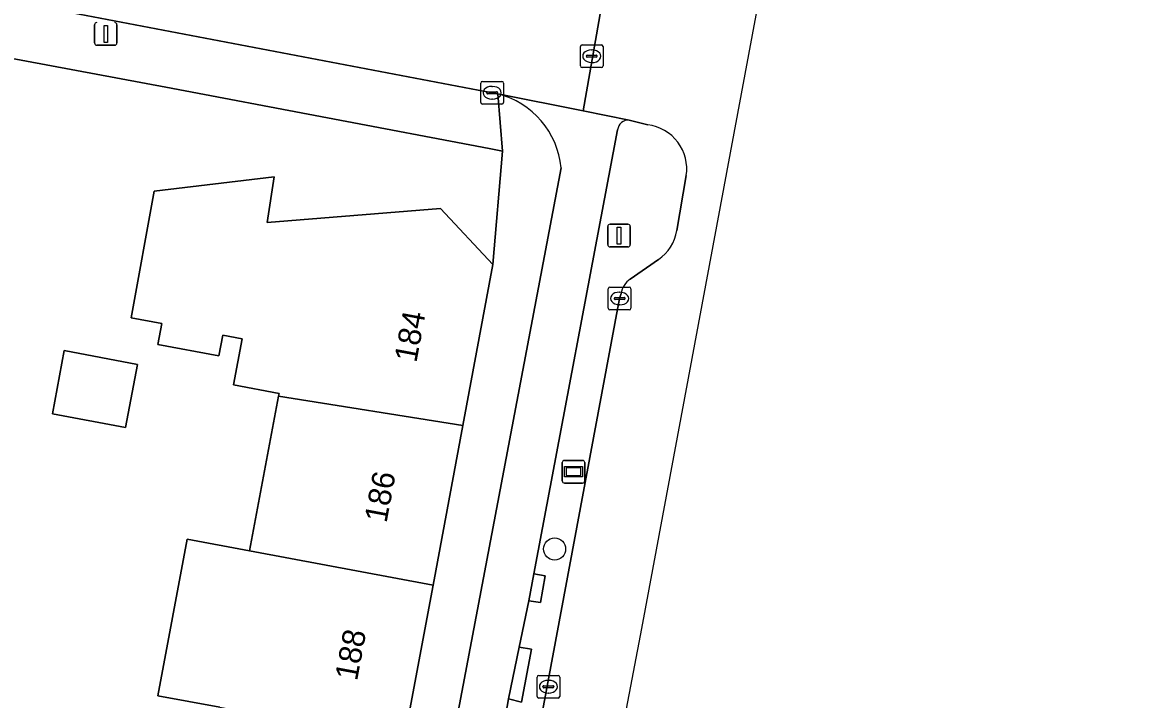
# Model space of a CAD drawing. Extents: x 161258 to 161838, y 380833 to 381727.
# Drawn here: x 161786.15 to 161835.77, y 381501.62 to 381531.46 of the extents above; entities that cross this region are included whole.
import ezdxf

# ---------------------------------------------------------------- set-up
doc = ezdxf.new("R2010")
doc.units = 0
for name, color, linetype in [('IMGEO_Berm_open', 7, 'Continuous'), ('IMGEO_Boom', 7, 'Continuous'), ('IMGEO_Erf', 7, 'Continuous'), ('IMGEO_Fietspad_open', 7, 'Continuous'), ('IMGEO_Kolk', 7, 'Continuous'), ('IMGEO_Lichtmast', 7, 'Continuous'), ('IMGEO_Pand', 7, 'Continuous'), ('IMGEO_Pand_nummerreeks', 7, 'Continuous'), ('IMGEO_Reclamebord', 7, 'Continuous'), ('IMGEO_Rijbaan_lokaal_open', 7, 'Continuous'), ('IMGEO_Rijbaan_regionaal_gesloten', 7, 'Continuous'), ('IMGEO_Rioolput', 7, 'Continuous'), ('IMGEO_Voetpad_open', 7, 'Continuous')]:
    doc.layers.add(name, color=color, linetype=linetype)

msp = doc.modelspace()

# ---------------------------------------------------------------- linework, layer by layer
at = {"layer": 'IMGEO_Berm_open'}
for points in [[(161813.737, 381526.947), (161812.916, 381527.15)], [(161812.402, 381526.729), (161808.703, 381507.157), (161809.2, 381507.077), (161809, 381505.901), (161808.478, 381505.969), (161808.057, 381503.928), (161808.598, 381503.831), (161808.168, 381501.508), (161807.583, 381501.645), (161807.282, 381499.872)], [(161815.011, 381522.292), (161815.427, 381524.711)], [(161812.951, 381520.152), (161814.198, 381521.007)], [(161805.513, 381482.046), (161808.875, 381500), (161812.487, 381519.293), (161812.558, 381519.511)]]:
    msp.add_lwpolyline(points, dxfattribs=at)
for centre, radius, start, end in [((161812.861, 381526.693), 0.46, 83.1072, 175.5323), ((161813.485, 381525), 1.964, 351.5445, 82.6204), ((161813.139, 381522.576), 1.893, 304.001, 351.3572), ((161813.495, 381519.377), 0.947, 125.0851, 171.8896)]:
    msp.add_arc(centre, radius, start, end, dxfattribs=at)
at = {"layer": 'IMGEO_Boom'}
msp.add_circle((161809.62, 381508.253), 0.489, dxfattribs=at)
at = {"layer": 'IMGEO_Erf'}
msp.add_lwpolyline([(161794.859, 381501.276), (161792.127, 381501.787), (161793.418, 381508.689), (161796.159, 381508.176), (161797.442, 381514.985), (161797.465, 381515.106), (161795.457, 381515.485), (161795.842, 381517.523), (161794.982, 381517.685), (161794.808, 381516.76), (161792.115, 381517.269), (161792.29, 381518.193), (161790.946, 381518.447), (161791.954, 381524.02), (161797.254, 381524.651), (161796.944, 381522.646), (161804.585, 381523.258), (161806.898, 381520.791), (161807.325, 381525.789), (161806.742, 381525.9), (161792.473, 381528.615), (161780.173, 381530.897)], dxfattribs=at)
msp.add_lwpolyline([(161787.468, 381514.215), (161787.994, 381516.997), (161791.223, 381516.388), (161790.697, 381513.606)], close=True, dxfattribs=at)
at = {"layer": 'IMGEO_Fietspad_open'}
for points in [[(161812.916, 381527.15), (161810.875, 381527.563), (161807.12, 381528.313)], [(161807.282, 381499.872), (161807.583, 381501.645), (161808.057, 381503.928), (161808.478, 381505.969), (161808.703, 381507.157), (161812.402, 381526.729)], [(161809.91, 381525.057), (161805.168, 381500)]]:
    msp.add_lwpolyline(points, dxfattribs=at)
for centre, radius, start, end in [((161806.195, 381524.697), 3.732, 5.5304, 75.6548), ((161812.861, 381526.693), 0.46, 83.1072, 175.5323)]:
    msp.add_arc(centre, radius, start, end, dxfattribs=at)
at = {"layer": 'IMGEO_Kolk'}
for p, q in [((161806.366, 381527.935), (161806.366, 381528.787)), ((161806.441, 381528.861), (161807.293, 381528.861)), ((161807.367, 381528.787), (161807.367, 381527.935)), ((161806.625, 381528.355), (161806.625, 381528.367)), ((161807.063, 381528.318), (161806.665, 381528.318)), ((161806.668, 381528.404), (161807.066, 381528.404)), ((161806.854, 381528.641), (161806.879, 381528.641)), ((161807.109, 381528.367), (161807.109, 381528.355)), ((161807.293, 381527.861), (161806.441, 381527.861)), ((161806.877, 381528.081), (161806.852, 381528.081)), ((161811.989, 381518.868), (161811.989, 381519.72)), ((161812.064, 381519.794), (161812.916, 381519.794)), ((161812.291, 381519.337), (161812.689, 381519.337)), ((161812.477, 381519.574), (161812.502, 381519.574)), ((161812.99, 381519.72), (161812.99, 381518.868)), ((161812.248, 381519.288), (161812.248, 381519.3)), ((161812.686, 381519.251), (161812.288, 381519.251)), ((161812.5, 381519.014), (161812.475, 381519.014)), ((161812.732, 381519.3), (161812.732, 381519.288)), ((161812.916, 381518.794), (161812.064, 381518.794)), ((161808.848, 381501.756), (161808.848, 381502.608)), ((161808.923, 381502.682), (161809.775, 381502.682)), ((161809.336, 381502.462), (161809.361, 381502.462)), ((161809.849, 381502.608), (161809.849, 381501.756)), ((161809.107, 381502.176), (161809.107, 381502.188)), ((161809.545, 381502.139), (161809.147, 381502.139)), ((161809.15, 381502.225), (161809.548, 381502.225)), ((161809.591, 381502.188), (161809.591, 381502.176)), ((161809.775, 381501.682), (161808.923, 381501.682)), ((161809.359, 381501.902), (161809.334, 381501.902))]:
    msp.add_line(p, q, dxfattribs=at)
for points in [[(161806.366, 381527.935), (161806.366, 381528.787)], [(161806.441, 381528.861), (161807.293, 381528.861)], [(161807.367, 381528.787), (161807.367, 381527.935)], [(161807.293, 381527.861), (161806.441, 381527.861)], [(161811.989, 381518.868), (161811.989, 381519.72)], [(161812.064, 381519.794), (161812.916, 381519.794)], [(161812.99, 381519.72), (161812.99, 381518.868)], [(161812.916, 381518.794), (161812.064, 381518.794)], [(161808.848, 381501.756), (161808.848, 381502.608)], [(161808.923, 381502.682), (161809.775, 381502.682)], [(161809.849, 381502.608), (161809.849, 381501.756)], [(161809.775, 381501.682), (161808.923, 381501.682)]]:
    msp.add_lwpolyline(points, dxfattribs=at)
for centre, radius, start, end in [((161806.443, 381528.785), 0.0765, 91.552, 178.448), ((161806.443, 381528.785), 0.0765, 91.552, 178.448), ((161807.291, 381528.785), 0.0765, 1.552, 88.448), ((161807.291, 381528.785), 0.0765, 1.552, 88.448), ((161806.665, 381528.364), 0.0403, 85.8775, 175.7526), ((161806.662, 381528.354), 0.0366, 178.938, 274.7102), ((161807.066, 381528.361), 0.043, 264.8664, 352.4533), ((161807.07, 381528.366), 0.0386, 1.7309, 96.639), ((161806.443, 381527.937), 0.0765, 181.552, 268.448), ((161806.443, 381527.937), 0.0765, 181.552, 268.448), ((161807.291, 381527.937), 0.0765, 271.552, 358.448), ((161807.291, 381527.937), 0.0765, 271.552, 358.448), ((161812.066, 381519.718), 0.0765, 91.552, 178.448), ((161812.066, 381519.718), 0.0765, 91.552, 178.448), ((161812.288, 381519.297), 0.0403, 85.8775, 175.7526), ((161812.693, 381519.299), 0.0386, 1.7309, 96.639), ((161812.914, 381519.718), 0.0765, 1.552, 88.448), ((161812.914, 381519.718), 0.0765, 1.552, 88.448), ((161812.066, 381518.87), 0.0765, 181.552, 268.448), ((161812.066, 381518.87), 0.0765, 181.552, 268.448), ((161812.285, 381519.287), 0.0366, 178.938, 274.7102), ((161812.689, 381519.294), 0.043, 264.8664, 352.4533), ((161812.914, 381518.87), 0.0765, 271.552, 358.448), ((161812.914, 381518.87), 0.0765, 271.552, 358.448), ((161808.925, 381502.606), 0.0765, 91.552, 178.448), ((161808.925, 381502.606), 0.0765, 91.552, 178.448), ((161809.773, 381502.606), 0.0765, 1.552, 88.448), ((161809.773, 381502.606), 0.0765, 1.552, 88.448), ((161809.147, 381502.185), 0.0403, 85.8775, 175.7526), ((161809.144, 381502.175), 0.0366, 178.938, 274.7102), ((161809.548, 381502.182), 0.043, 264.8664, 352.4533), ((161809.552, 381502.187), 0.0386, 1.7309, 96.639), ((161808.925, 381501.758), 0.0765, 181.552, 268.448), ((161808.925, 381501.758), 0.0765, 181.552, 268.448), ((161809.773, 381501.758), 0.0765, 271.552, 358.448), ((161809.773, 381501.758), 0.0765, 271.552, 358.448)]:
    msp.add_arc(centre, radius, start, end, dxfattribs=at)
for centre, major_axis, ratio, start_param, end_param in [((161806.853, 381528.361), (-0.387, 0.002), 0.722429, 4.712389, 7.853982), ((161806.878, 381528.361), (-0.39, 0.002), 0.717154, 1.570796, 4.712389), ((161812.476, 381519.294), (-0.387, 0.002), 0.722429, 4.712389, 7.853982), ((161812.501, 381519.294), (-0.39, 0.002), 0.717154, 1.570796, 4.712389), ((161809.335, 381502.182), (-0.387, 0.002), 0.722429, 4.712389, 7.853982), ((161809.36, 381502.182), (-0.39, 0.002), 0.717154, 1.570796, 4.712389)]:
    msp.add_ellipse(centre, major_axis=major_axis, ratio=ratio, start_param=start_param, end_param=end_param, dxfattribs=at)
at = {"layer": 'IMGEO_Lichtmast'}
for p, q in [((161789.327, 381530.559), (161789.327, 381531.359)), ((161789.327, 381531.359), (161789.327, 381530.559)), ((161790.317, 381531.359), (161790.317, 381530.559)), ((161790.317, 381530.559), (161790.317, 381531.359)), ((161790.217, 381530.459), (161789.427, 381530.459)), ((161789.427, 381530.459), (161790.217, 381530.459)), ((161811.967, 381521.669), (161811.967, 381522.469)), ((161811.967, 381522.469), (161811.967, 381521.669)), ((161812.067, 381522.569), (161812.857, 381522.569)), ((161812.857, 381522.569), (161812.067, 381522.569)), ((161812.957, 381522.469), (161812.957, 381521.669)), ((161812.957, 381521.669), (161812.957, 381522.469)), ((161812.857, 381521.569), (161812.067, 381521.569)), ((161812.067, 381521.569), (161812.857, 381521.569))]:
    msp.add_line(p, q, dxfattribs=at)
for points in [[(161789.747, 381531.334), (161789.897, 381531.334), (161789.897, 381530.584), (161789.747, 381530.584), (161789.747, 381531.334)], [(161812.387, 381522.444), (161812.537, 381522.444), (161812.537, 381521.694), (161812.387, 381521.694), (161812.387, 381522.444)]]:
    msp.add_lwpolyline(points, dxfattribs=at)
for centre, start, end in [((161789.427, 381531.359), 90, 180), ((161789.427, 381531.359), 90, 180), ((161790.217, 381531.359), 0, 90), ((161790.217, 381531.359), 360, 90), ((161789.427, 381530.559), 180, 270), ((161789.427, 381530.559), 180, 270), ((161790.217, 381530.559), 270, 0), ((161790.217, 381530.559), 270, 0), ((161812.067, 381522.469), 90, 180), ((161812.067, 381522.469), 90, 180), ((161812.857, 381522.469), 0, 90), ((161812.857, 381522.469), 360, 90), ((161812.067, 381521.669), 180, 270), ((161812.067, 381521.669), 180, 270), ((161812.857, 381521.669), 270, 0), ((161812.857, 381521.669), 270, 0)]:
    msp.add_arc(centre, 0.1, start, end, dxfattribs=at)
at = {"layer": 'IMGEO_Pand'}
for points in [[(161806.898, 381520.791), (161804.585, 381523.258), (161796.944, 381522.646), (161797.254, 381524.651), (161791.954, 381524.02), (161790.946, 381518.447), (161792.29, 381518.193), (161792.115, 381517.269), (161794.808, 381516.76), (161794.982, 381517.685), (161795.842, 381517.523), (161795.457, 381515.485), (161797.465, 381515.106), (161797.442, 381514.985), (161805.574, 381513.691)], [(161787.468, 381514.215), (161790.697, 381513.606), (161791.223, 381516.388), (161787.994, 381516.997)], [(161804.264, 381506.66), (161805.574, 381513.691), (161797.442, 381514.985), (161796.159, 381508.176)], [(161804.264, 381506.66), (161796.159, 381508.176), (161793.418, 381508.689), (161792.127, 381501.787), (161794.859, 381501.276), (161801.684, 381500), (161802.977, 381499.759), (161803.022, 381500)]]:
    msp.add_lwpolyline(points, close=True, dxfattribs=at)
at = {"layer": 'IMGEO_Reclamebord'}
for p, q in [((161809.96, 381511.259), (161809.96, 381512.059)), ((161809.96, 381512.059), (161809.96, 381511.259)), ((161810.06, 381512.159), (161810.85, 381512.159)), ((161810.85, 381512.159), (161810.06, 381512.159)), ((161810.95, 381512.059), (161810.95, 381511.259)), ((161810.95, 381511.259), (161810.95, 381512.059)), ((161810.85, 381511.159), (161810.06, 381511.159)), ((161810.06, 381511.159), (161810.85, 381511.159))]:
    msp.add_line(p, q, dxfattribs=at)
for points in [[(161810.061, 381511.891), (161810.849, 381511.891), (161810.849, 381511.427), (161810.061, 381511.427), (161810.061, 381511.891)], [(161810.126, 381511.826), (161810.126, 381511.492), (161810.784, 381511.492), (161810.784, 381511.826), (161810.126, 381511.826)]]:
    msp.add_lwpolyline(points, dxfattribs=at)
for centre, start, end in [((161810.06, 381512.059), 90, 180), ((161810.06, 381512.059), 90, 180), ((161810.85, 381512.059), 0, 90), ((161810.85, 381512.059), 360, 90), ((161810.06, 381511.259), 180, 270), ((161810.06, 381511.259), 180, 270), ((161810.85, 381511.259), 270, 0), ((161810.85, 381511.259), 270, 0)]:
    msp.add_arc(centre, 0.1, start, end, dxfattribs=at)
at = {"layer": 'IMGEO_Rijbaan_lokaal_open'}
msp.add_lwpolyline([(161786.693, 381537.202), (161786.472, 381537.226), (161780.553, 381538.362), (161779.615, 381533.541), (161785.57, 381532.417), (161806.867, 381528.363), (161807.12, 381528.313), (161810.875, 381527.563), (161811.823, 381532.939)], dxfattribs=at)
at = {"layer": 'IMGEO_Rijbaan_regionaal_gesloten'}
for points in [[(161732.705, 381071.484), (161732.705, 381071.238), (161742.349, 381122.541), (161776.386, 381306.634), (161779.513, 381323.547), (161779.709, 381323.516), (161781.032, 381330.976), (161790.829, 381386.201), (161813.475, 381504.752), (161831.216, 381599.902), (161831.886, 381604.233), (161835.772, 381629.362), (161830.258, 381630.974)], [(161811.823, 381532.939), (161810.875, 381527.563), (161812.916, 381527.15), (161813.737, 381526.947)], [(161815.427, 381524.711), (161815.011, 381522.292)], [(161814.198, 381521.007), (161812.951, 381520.152)], [(161812.558, 381519.511), (161812.487, 381519.293), (161808.875, 381500), (161805.513, 381482.046), (161802.827, 381467.862), (161798.642, 381445.853), (161795.675, 381429.807), (161795.205, 381427.327), (161795.046, 381426.438)]]:
    msp.add_lwpolyline(points, dxfattribs=at)
for centre, radius, start, end in [((161813.485, 381525), 1.964, 351.5445, 82.6204), ((161813.139, 381522.576), 1.893, 304.001, 351.3572), ((161813.495, 381519.377), 0.947, 125.0851, 171.8896)]:
    msp.add_arc(centre, radius, start, end, dxfattribs=at)
at = {"layer": 'IMGEO_Rioolput'}
for p, q in [((161810.759, 381529.548), (161810.759, 381530.4)), ((161810.834, 381530.474), (161811.686, 381530.474)), ((161811.247, 381530.254), (161811.272, 381530.254)), ((161811.76, 381530.4), (161811.76, 381529.548)), ((161811.018, 381529.968), (161811.018, 381529.98)), ((161811.456, 381529.931), (161811.058, 381529.931)), ((161811.061, 381530.017), (161811.459, 381530.017)), ((161811.502, 381529.98), (161811.502, 381529.968)), ((161811.686, 381529.474), (161810.834, 381529.474)), ((161811.27, 381529.694), (161811.245, 381529.694))]:
    msp.add_line(p, q, dxfattribs=at)
for points in [[(161810.759, 381529.548), (161810.759, 381530.4)], [(161810.834, 381530.474), (161811.686, 381530.474)], [(161811.76, 381530.4), (161811.76, 381529.548)], [(161811.686, 381529.474), (161810.834, 381529.474)]]:
    msp.add_lwpolyline(points, dxfattribs=at)
for centre, radius, start, end in [((161810.836, 381530.398), 0.0765, 91.552, 178.448), ((161810.836, 381530.398), 0.0765, 91.552, 178.448), ((161811.684, 381530.398), 0.0765, 1.552, 88.448), ((161811.684, 381530.398), 0.0765, 1.552, 88.448), ((161811.058, 381529.977), 0.0403, 85.8775, 175.7526), ((161811.055, 381529.967), 0.0366, 178.938, 274.7102), ((161811.459, 381529.974), 0.043, 264.8664, 352.4533), ((161811.463, 381529.979), 0.0386, 1.7309, 96.639), ((161810.836, 381529.55), 0.0765, 181.552, 268.448), ((161810.836, 381529.55), 0.0765, 181.552, 268.448), ((161811.684, 381529.55), 0.0765, 271.552, 358.448), ((161811.684, 381529.55), 0.0765, 271.552, 358.448)]:
    msp.add_arc(centre, radius, start, end, dxfattribs=at)
for centre, major_axis, ratio, start_param, end_param in [((161811.246, 381529.974), (-0.387, 0.002), 0.722429, 4.712389, 7.853982), ((161811.271, 381529.974), (-0.39, 0.002), 0.717154, 1.570796, 4.712389)]:
    msp.add_ellipse(centre, major_axis=major_axis, ratio=ratio, start_param=start_param, end_param=end_param, dxfattribs=at)
at = {"layer": 'IMGEO_Voetpad_open'}
for points in [[(161779.615, 381533.541), (161774.842, 381534.445), (161768.171, 381535.745), (161763.484, 381536.649), (161762.151, 381536.852), (161742.121, 381540.664), (161741.669, 381540.75), (161741.711, 381538.033), (161779.178, 381531.082), (161780.173, 381530.897), (161792.473, 381528.615), (161806.742, 381525.9), (161807.325, 381525.789), (161807.12, 381528.313), (161806.867, 381528.363), (161785.57, 381532.417)], [(161809.2, 381507.077), (161808.703, 381507.157), (161808.478, 381505.969), (161809, 381505.901)], [(161808.598, 381503.831), (161808.057, 381503.928), (161807.583, 381501.645), (161808.168, 381501.508)]]:
    msp.add_lwpolyline(points, close=True, dxfattribs=at)
for points in [[(161807.12, 381528.313), (161807.325, 381525.789), (161806.898, 381520.791), (161805.574, 381513.691), (161804.264, 381506.66), (161803.022, 381500)], [(161774.147, 381338.339), (161776.847, 381352.346), (161788.338, 381413.247), (161792.085, 381430.647), (161795.911, 381451.079), (161805.168, 381500), (161809.91, 381525.057)]]:
    msp.add_lwpolyline(points, dxfattribs=at)
msp.add_arc((161806.195, 381524.697), 3.732, 5.5304, 75.6548, dxfattribs=at)

# ---------------------------------------------------------------- texts
at = {"layer": 'IMGEO_Pand_nummerreeks'}
for s, rotation, p in [('184', 79.4406, (161803.523, 381516.437)), ('186', 79.4398, (161802.206, 381509.372)), ('188', 79.4398, (161800.907, 381502.41))]:
    msp.add_text(s, height=1, rotation=rotation, dxfattribs=at).set_placement(p)

doc.saveas('drawing.dxf')
